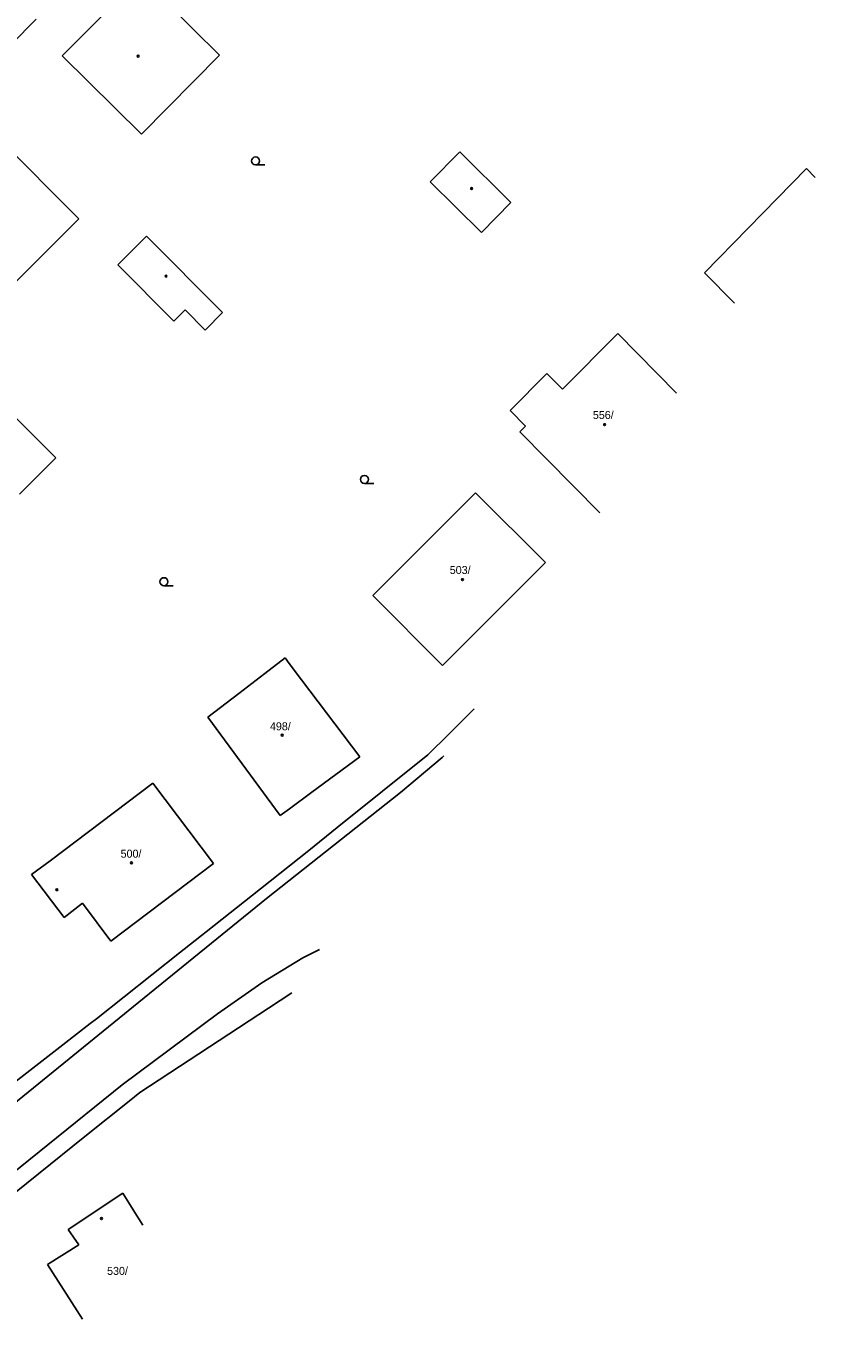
# Model space of a CAD drawing. Extents: x -737488 to -734267, y -1145775 to -1142573.
# Drawn here: x -736559.5 to -736485.5, y -1144426.2 to -1144304.9 of the extents above; entities that cross this region are included whole.
import ezdxf

# ---------------------------------------------------------------- set-up
doc = ezdxf.new("R2010")
doc.units = 0
for name, color, linetype in [('Vrstva 1', 7, 'Continuous'), ('Vrstva 10', 7, 'Continuous'), ('Vrstva 3', 7, 'Continuous'), ('Vrstva 5', 7, 'Continuous'), ('Vrstva 6', 7, 'Continuous'), ('Vrstva 8', 7, 'Continuous'), ('Vrstva 9', 7, 'Continuous')]:
    doc.layers.add(name, color=color, linetype=linetype)

# ---------------------------------------------------------------- blocks, each defined once
blk = doc.blocks.new('3.040')
at = {"layer": 'Vrstva 1'}
blk.add_line((0, -0.75), (1.75, -0.75), dxfattribs=at)
blk.add_circle((0, 0), 0.75, dxfattribs=at)
blk = doc.blocks.new('4.020')
at = {"layer": 'Vrstva 1'}
blk.add_circle((0, 0), 0.175, dxfattribs=at)

msp = doc.modelspace()

# ---------------------------------------------------------------- linework, layer by layer
at = {"layer": 'Vrstva 10'}
for points in [[(-736524.39, -1144376.8), (-736520.48, -1144373.52)], [(-736520.48, -1144373.52), (-736520.3, -1144373.35)], [(-736536.94, -1144386.73), (-736524.39, -1144376.8)], [(-736548.88, -1144396.44), (-736536.94, -1144386.73)], [(-736537.38, -1144394.65), (-736533.54, -1144392.29)], [(-736533.54, -1144392.29), (-736531.96, -1144391.52)], [(-736541.52, -1144397.55), (-736537.38, -1144394.65)], [(-736567.32, -1144411.42), (-736548.88, -1144396.44)], [(-736550.45, -1144404.19), (-736541.52, -1144397.55)], [(-736564.42, -1144415.46), (-736550.45, -1144404.19)]]:
    msp.add_lwpolyline(points, dxfattribs=at)
at = {"layer": 'Vrstva 5'}
for points in [[(-736556.07, -1144307.75), (-736548.75, -1144300.35)], [(-736548.75, -1144300.35), (-736541.34, -1144307.68)], [(-736548.66, -1144315.08), (-736556.07, -1144307.75)], [(-736541.34, -1144307.68), (-736548.66, -1144315.08)], [(-736554.51, -1144323.03), (-736562.05, -1144315.49)], [(-736518.83, -1144316.76), (-736521.6, -1144319.57)], [(-736514.03, -1144321.5), (-736518.83, -1144316.76)], [(-736495.9, -1144328.08), (-736486.34, -1144318.31)], [(-736486.34, -1144318.31), (-736485.52, -1144319.14)], [(-736521.6, -1144319.57), (-736516.8, -1144324.31)], [(-736516.8, -1144324.31), (-736514.03, -1144321.5)], [(-736561.63, -1144330.16), (-736554.51, -1144323.03)], [(-736550.87, -1144327.34), (-736548.17, -1144324.65)], [(-736548.17, -1144324.65), (-736541.05, -1144331.81)], [(-736545.62, -1144332.62), (-736550.87, -1144327.34)], [(-736493.09, -1144330.93), (-736495.9, -1144328.08)], [(-736544.55, -1144331.57), (-736545.62, -1144332.62)], [(-736542.68, -1144333.46), (-736544.55, -1144331.57)], [(-736541.05, -1144331.81), (-736542.68, -1144333.46)], [(-736509.18, -1144338.99), (-736504.02, -1144333.79)], [(-736504.02, -1144333.79), (-736498.5, -1144339.37)], [(-736514.09, -1144341), (-736510.65, -1144337.53)], [(-736510.65, -1144337.53), (-736509.18, -1144338.99)], [(-736556.68, -1144345.42), (-736561.67, -1144340.44)], [(-736512.65, -1144342.45), (-736514.09, -1144341)], [(-736513.18, -1144342.98), (-736512.65, -1144342.45)], [(-736505.69, -1144350.58), (-736513.18, -1144342.98)], [(-736560.09, -1144348.83), (-736556.68, -1144345.42)], [(-736517.34, -1144348.71), (-736526.97, -1144358.35)], [(-736510.8, -1144355.25), (-736517.34, -1144348.71)], [(-736520.43, -1144364.89), (-736510.8, -1144355.25)], [(-736526.97, -1144358.35), (-736520.43, -1144364.89)], [(-736535.18, -1144364.19), (-736537.09, -1144365.65)], [(-736534.8, -1144364.7), (-736535.18, -1144364.19)], [(-736533.64, -1144366.24), (-736534.8, -1144364.7)], [(-736537.09, -1144365.65), (-736539.52, -1144367.51)], [(-736528.2, -1144373.47), (-736533.64, -1144366.24)], [(-736539.52, -1144367.51), (-736542.44, -1144369.75)], [(-736542.44, -1144369.75), (-736535.64, -1144378.96)], [(-736532.67, -1144376.77), (-736528.2, -1144373.47)], [(-736547.59, -1144375.94), (-736557.2, -1144383.21)], [(-736541.9, -1144383.47), (-736547.59, -1144375.94)], [(-736534.78, -1144378.33), (-736532.67, -1144376.77)], [(-736535.64, -1144378.96), (-736534.78, -1144378.33)], [(-736557.2, -1144383.21), (-736558.96, -1144384.48)], [(-736551.51, -1144390.74), (-736541.9, -1144383.47)], [(-736558.96, -1144384.48), (-736555.88, -1144388.53)], [(-736555.88, -1144388.53), (-736554.18, -1144387.19)], [(-736554.18, -1144387.19), (-736551.51, -1144390.74)], [(-736550.4, -1144414.36), (-736555.51, -1144417.75)], [(-736549.43, -1144415.93), (-736550.4, -1144414.36)], [(-736548.52, -1144417.35), (-736549.43, -1144415.93)], [(-736555.51, -1144417.75), (-736554.52, -1144419.2)], [(-736554.52, -1144419.2), (-736557.45, -1144421.06)], [(-736557.45, -1144421.06), (-736554.18, -1144426.17)]]:
    msp.add_lwpolyline(points, dxfattribs=at)
at = {"layer": 'Vrstva 9'}
for points in [[(-736558.51, -1144304.31), (-736563.14, -1144308.96)], [(-736519.81, -1144371.29), (-736517.48, -1144368.95)], [(-736521.82, -1144373.27), (-736519.81, -1144371.29)], [(-736530.3, -1144380.07), (-736521.82, -1144373.27)], [(-736532.98, -1144382.25), (-736530.3, -1144380.07)], [(-736537.49, -1144385.84), (-736532.98, -1144382.25)], [(-736542.57, -1144389.86), (-736537.49, -1144385.84)], [(-736545.1, -1144391.82), (-736542.57, -1144389.86)], [(-736552.85, -1144398.02), (-736545.1, -1144391.82)], [(-736536.75, -1144397.01), (-736534.57, -1144395.59)], [(-736536.75, -1144397.01), (-736548.8, -1144404.93)], [(-736556.01, -1144400.45), (-736553.44, -1144398.46)], [(-736553.44, -1144398.46), (-736552.85, -1144398.02)], [(-736562.81, -1144405.69), (-736556.01, -1144400.45)], [(-736553.94, -1144409.06), (-736549.79, -1144405.72)], [(-736549.79, -1144405.72), (-736548.8, -1144404.93)], [(-736553.94, -1144409.06), (-736567.02, -1144419.53)]]:
    msp.add_lwpolyline(points, dxfattribs=at)

# ---------------------------------------------------------------- block references
at = {"layer": 'Vrstva 3', "xscale": 0.5, "yscale": 0.5}
for p in [(-736537.96, -1144317.6), (-736527.75, -1144347.45), (-736546.54, -1144357.04)]:
    msp.add_blockref('3.040', p, dxfattribs=at)
at = {"layer": 'Vrstva 8', "xscale": 0.5, "yscale": 0.5}
for p in [(-736548.96, -1144307.78), (-736517.71, -1144320.19), (-736546.35, -1144328.4), (-736505.25, -1144342.32), (-736518.57, -1144356.85), (-736535.46, -1144371.42), (-736549.59, -1144383.39), (-736556.57, -1144385.91), (-736552.4, -1144416.74)]:
    msp.add_blockref('4.020', p, dxfattribs=at)

# ---------------------------------------------------------------- texts
at = {"layer": 'Vrstva 6'}
for s, p in [('556/', (-736506.35, -1144341.79)), ('503/', (-736519.76, -1144356.32)), ('498/', (-736536.61, -1144370.97)), ('500/', (-736550.6, -1144382.91)), ('530/', (-736551.87, -1144422.02))]:
    msp.add_text(s, height=0.75, dxfattribs=at).set_placement(p)

doc.saveas('drawing.dxf')
